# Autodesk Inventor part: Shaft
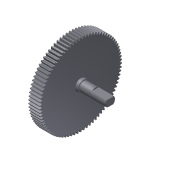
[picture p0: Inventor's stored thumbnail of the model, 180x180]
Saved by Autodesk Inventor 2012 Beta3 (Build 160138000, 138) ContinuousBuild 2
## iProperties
Created: 2010-12
Part Number: Shaft
Material: Steel
Document SubType Name: Modeling
Designer: Thom Tremblay
Density: 1 g/cm^3
CustomPartVersion: 1
Author: Thom Tremblay
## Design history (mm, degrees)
sketch "Main Sketch"
  geometry: L1 (0, 0)-(43, 0) reference; L2 (0, 0)-(0, 45); L3 (12, 45)-(12, 6); L4 (0, 45)-(12, 45); L5 (15, 6)-(15, 5); L6 (12, 6)-(15, 6); L7 (43, 5)-(43, 0); L8 (15, 5)-(43, 5)
  constraints: 16 end point, 4 vertical, 2 horizontal
  dimensions: "d3" = 90 diameter of L4 L1 (derived); "d4" = 12 diameter of L6 L1 (derived); "d5" = 10 diameter of L8 L1 (derived)
revolve "Revolution1" sketch "Main Sketch" stored, may be unused: angle "d6" = 0 deg
node "Retaining Ring Groove1"
chamfer "Chamfer1" distance "d7" = 0.5; stored, may be unused: second distance "d8" = 0.125, angle "d9" = 45 deg
chamfer "Chamfer2" distance "d10" = 0.5; stored, may be unused: second distance "d11" = 0.125, angle "d12" = 45 deg
node "Spur Gear Teeth1"
sketch "Sketch3"
  geometry: L1 (-3.5, 3.571)-(-3.5, -3.571); L2 (3.5, 3.571)-(3.5, -3.571); A1 r 5 centre (0, 0) between (-3.5, 3.571) and (-3.5, -3.571) reference; 1 further point
  constraints: 4 end point, 4 point on circle, 2 parallel, 1 vertical
  dimensions: "d13" = 7 distance between parallel lines of L2 L1
extrude "Extrusion1" cut sketch "Sketch3" distance "d14" = 16; taper "d15" = 0 deg
node "Hole2"
body "Solid1"
feature "Spur Gear2"
feature "iFeature27:1"
sketch "Sketch4"
  geometry: 1 further point
hole "Hole1" sketch "Sketch4" diameter "d16" = 3.242; stored, may be unused: countersink angle "d20" = 90 deg, drill point angle "d22" = 120 deg; dims "d17" = 8, "d18" = 4, "d19" = 2, "d21" = 10
other parameters: "d0" = 0, "d1" = 0, "d2" = 0
